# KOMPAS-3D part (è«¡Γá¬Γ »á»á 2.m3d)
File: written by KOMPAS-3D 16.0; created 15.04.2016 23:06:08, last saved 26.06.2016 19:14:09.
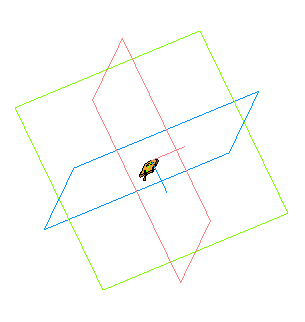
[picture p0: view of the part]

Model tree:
1. Эскиз:1
2. Операция выдавливания:1
     Расстояние 1 = 0.5
3. Фаска:1
     Угол = 45; Длина 1 = 1; Длина 2 = 1
4. Эскиз:10
5. Операция выдавливания:7
     Расстояние 1 = 2
6. Эскиз:11
7. Операция выдавливания:8
     Расстояние 1 = 1; Расстояние 2 = 1.4
8. Эскиз:12
9. Вырезать элемент выдавливания:3
     Расстояние 1 = 10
